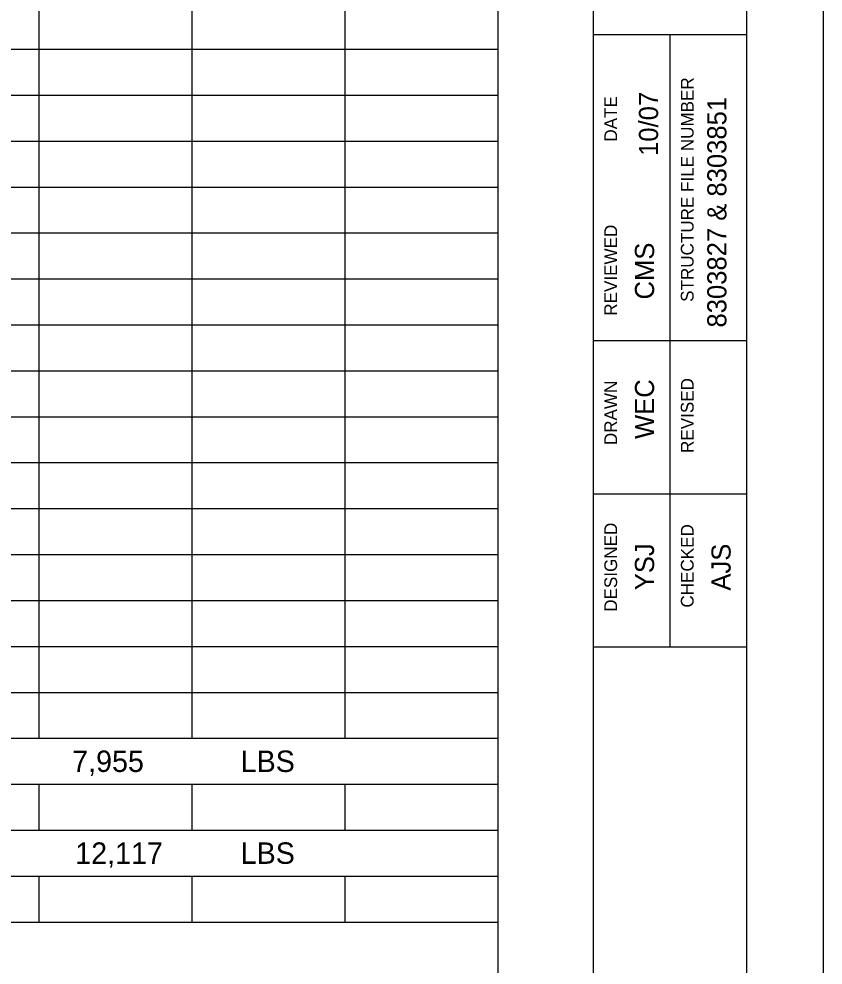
# Model space of a CAD drawing. Extents: x 1485751 to 1485785, y 230696.6 to 230718.6.
# Drawn here: x 1485779.78 to 1485785.03, y 230708.56 to 230714.74 of the extents above; entities that cross this region are included whole.
import ezdxf

# ---------------------------------------------------------------- set-up
doc = ezdxf.new("R2010")
doc.units = 0
for name, color, linetype in [('SH_Border', 7, 'Continuous'), ('SH_Cut_Line', 7, 'Continuous'), ('SH_Data', 7, 'Continuous'), ('TX_P_Misc', 7, 'Continuous')]:
    doc.layers.add(name, color=color, linetype=linetype)

msp = doc.modelspace()

# ---------------------------------------------------------------- linework, layer by layer
at = {"layer": 'SH_Border'}
for p, q in [((1485783.5329, 230697.1408), (1485783.5329, 230718.1408)), ((1485783.5329, 230697.1408), (1485783.5329, 230718.1408)), ((1485783.5329, 230697.1408), (1485783.5329, 230718.1408)), ((1485783.5329, 230714.6408), (1485784.5329, 230714.6408)), ((1485783.5329, 230714.6408), (1485784.5329, 230714.6408)), ((1485783.5329, 230714.6408), (1485784.5329, 230714.6408)), ((1485784.0329, 230710.6408), (1485784.0329, 230714.6408)), ((1485784.0329, 230710.6408), (1485784.0329, 230714.6408)), ((1485784.0329, 230710.6408), (1485784.0329, 230714.6408)), ((1485783.5329, 230712.6408), (1485784.5329, 230712.6408)), ((1485783.5329, 230712.6408), (1485784.5329, 230712.6408)), ((1485783.5329, 230712.6408), (1485784.5329, 230712.6408)), ((1485783.5329, 230711.6408), (1485784.5329, 230711.6408)), ((1485783.5329, 230711.6408), (1485784.5329, 230711.6408)), ((1485783.5329, 230711.6408), (1485784.5329, 230711.6408)), ((1485783.5329, 230710.6408), (1485784.5329, 230710.6408)), ((1485783.5329, 230710.6408), (1485784.5329, 230710.6408)), ((1485783.5329, 230710.6408), (1485784.5329, 230710.6408))]:
    msp.add_line(p, q, dxfattribs=at)
msp.add_lwpolyline([(1485753.0329, 230718.1408), (1485784.5329, 230718.1408), (1485784.5329, 230697.1408), (1485753.0329, 230697.1408)], close=True, dxfattribs=at)
at = {"layer": 'SH_Cut_Line'}
msp.add_lwpolyline([(1485751.0329, 230718.6408), (1485785.0329, 230718.6408), (1485785.0329, 230696.6408), (1485751.0329, 230696.6408)], close=True, dxfattribs=at)
at = {"layer": 'TX_P_Misc'}
for p, q in [((1485779.9079, 230717.394), (1485779.9079, 230710.044)), ((1485780.9079, 230717.394), (1485780.9079, 230710.044)), ((1485781.9079, 230717.394), (1485781.9079, 230710.044)), ((1485782.9079, 230717.394), (1485782.9079, 230699.244)), ((1485773.6579, 230714.544), (1485782.9079, 230714.544)), ((1485773.6579, 230714.244), (1485782.9079, 230714.244)), ((1485773.6579, 230713.944), (1485782.9079, 230713.944)), ((1485773.6579, 230713.644), (1485782.9079, 230713.644)), ((1485773.6579, 230713.344), (1485782.9079, 230713.344)), ((1485773.6579, 230713.044), (1485782.9079, 230713.044)), ((1485773.6579, 230712.744), (1485782.9079, 230712.744)), ((1485773.6579, 230712.444), (1485782.9079, 230712.444)), ((1485773.6579, 230712.144), (1485782.9079, 230712.144)), ((1485773.6579, 230711.844), (1485782.9079, 230711.844)), ((1485773.6579, 230711.544), (1485782.9079, 230711.544)), ((1485773.6579, 230711.244), (1485782.9079, 230711.244)), ((1485773.6579, 230710.944), (1485782.9079, 230710.944)), ((1485773.6579, 230710.644), (1485782.9079, 230710.644)), ((1485773.6579, 230710.344), (1485782.9079, 230710.344)), ((1485773.6579, 230710.044), (1485782.9079, 230710.044)), ((1485773.6579, 230709.744), (1485782.9079, 230709.744)), ((1485779.9079, 230709.744), (1485779.9079, 230709.444)), ((1485780.9079, 230709.744), (1485780.9079, 230709.444)), ((1485781.9079, 230709.744), (1485781.9079, 230709.444)), ((1485773.6579, 230709.444), (1485782.9079, 230709.444)), ((1485773.6579, 230709.144), (1485782.9079, 230709.144)), ((1485779.9079, 230709.144), (1485779.9079, 230708.844)), ((1485780.9079, 230709.144), (1485780.9079, 230708.844)), ((1485781.9079, 230709.144), (1485781.9079, 230708.844)), ((1485773.6579, 230708.844), (1485782.9079, 230708.844))]:
    msp.add_line(p, q, dxfattribs=at)

# ---------------------------------------------------------------- texts
at = {"layer": 'SH_Data'}
for s, height, p in [('STRUCTURE FILE NUMBER', 0.0833, (1485784.187, 230712.8938)), ('DATE', 0.0833, (1485783.687, 230713.9405)), ('10/07', 0.125, (1485783.9549, 230713.8469)), ('8303827 & 8303851', 0.125, (1485784.4012, 230712.7264)), ('REVIEWED', 0.0833, (1485783.687, 230712.8035)), ('CMS', 0.125, (1485783.9287, 230712.9095)), ('WEC', 0.125, (1485783.9287, 230711.9985)), ('REVISED', 0.0833, (1485784.187, 230711.9073)), ('DRAWN', 0.0833, (1485783.687, 230711.9585)), ('DESIGNED', 0.0833, (1485783.687, 230710.87)), ('CHECKED', 0.0833, (1485784.187, 230710.8975)), ('YSJ', 0.125, (1485783.9287, 230711.0108)), ('AJS', 0.125, (1485784.4287, 230711.0083))]:
    msp.add_text(s, height=height, rotation=90, dxfattribs=at).set_placement(p)
at = {"layer": 'TX_P_Misc'}
for s, p in [('7,955', (1485780.1268, 230709.824)), ('LBS', (1485781.2276, 230709.824)), ('12,117', (1485780.1467, 230709.224)), ('LBS', (1485781.2276, 230709.224))]:
    msp.add_text(s, height=0.14, dxfattribs=at).set_placement(p)

doc.saveas('drawing.dxf')
